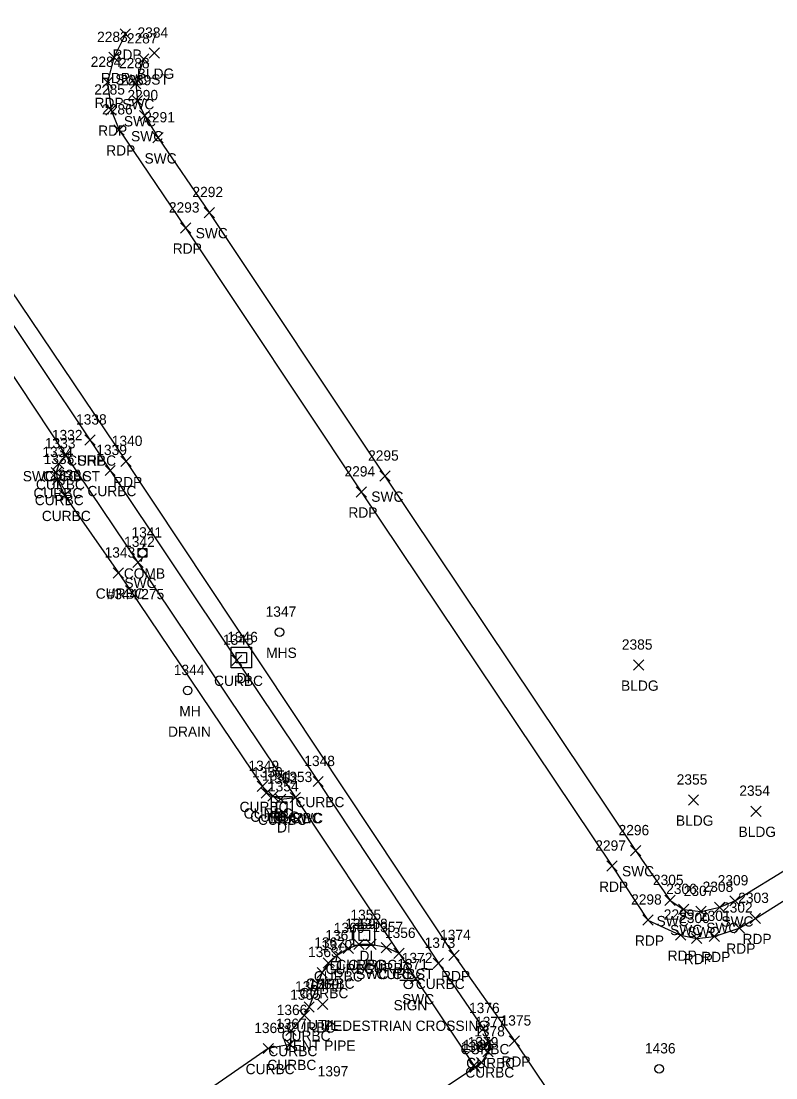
# Model space of a CAD drawing. Extents: x 1635588 to 1637550, y 621583 to 623638.
# Drawn here: x 1636890.8 to 1637037.4, y 622269.5 to 622475 of the extents above; entities that cross this region are included whole.
import ezdxf

# ---------------------------------------------------------------- set-up
doc = ezdxf.new("R2010")
doc.units = 0
for name, color, linetype in [('D_A', 7, 'Continuous'), ('D_I', 7, 'Continuous'), ('DS', 7, 'Continuous'), ('L_A', 7, 'Continuous'), ('L_I', 7, 'Continuous'), ('L_TIC', 7, 'Continuous'), ('P_A', 7, 'Continuous'), ('P_I', 7, 'Continuous'), ('P_TIC', 7, 'Continuous'), ('PET', 7, 'Continuous'), ('PSP', 7, 'Continuous'), ('R_A', 7, 'Continuous'), ('R_I', 7, 'Continuous'), ('R_TIC', 7, 'Continuous'), ('RC', 7, 'Continuous'), ('RSW', 7, 'Continuous'), ('S_A', 7, 'Continuous'), ('S_C', 7, 'Continuous'), ('S_I', 7, 'Continuous'), ('SSGN', 7, 'Continuous'), ('U_A', 7, 'Continuous'), ('U_C', 7, 'Continuous'), ('U_I', 7, 'Continuous'), ('UDEFAULT', 7, 'Continuous'), ('ULP', 7, 'Continuous'), ('UP', 7, 'Continuous'), ('USMH', 7, 'Continuous'), ('UUMH', 7, 'Continuous')]:
    doc.layers.add(name, color=color, linetype=linetype)

msp = doc.modelspace()

# ---------------------------------------------------------------- linework, layer by layer
at = {"layer": 'DS'}
for p, q in [((1636931.56, 622353.25), (1636935.56, 622353.25)), ((1636931.56, 622349.25), (1636931.56, 622353.25)), ((1636935.56, 622353.25), (1636935.56, 622349.25)), ((1636932.56, 622350.25), (1636932.56, 622352.25)), ((1636932.56, 622352.25), (1636934.56, 622352.25)), ((1636933.57, 622351.25), (1636933.57, 622351.25)), ((1636933.57, 622351.25), (1636933.57, 622351.25)), ((1636934.56, 622352.25), (1636934.56, 622350.25)), ((1636935.56, 622349.25), (1636931.56, 622349.25)), ((1636934.56, 622350.25), (1636932.56, 622350.25)), ((1636939.43, 622324.22), (1636943.43, 622324.22)), ((1636939.43, 622320.22), (1636939.43, 622324.22)), ((1636943.43, 622324.22), (1636943.43, 622320.22)), ((1636940.43, 622321.22), (1636940.43, 622323.22)), ((1636940.43, 622323.22), (1636942.43, 622323.22)), ((1636941.44, 622322.23), (1636941.44, 622322.23)), ((1636941.44, 622322.23), (1636941.44, 622322.23)), ((1636942.43, 622323.22), (1636942.43, 622321.22)), ((1636943.43, 622320.22), (1636939.43, 622320.22)), ((1636942.43, 622321.22), (1636940.43, 622321.22)), ((1636955.45, 622299.24), (1636959.45, 622299.24)), ((1636955.45, 622295.24), (1636955.45, 622299.24)), ((1636959.45, 622299.24), (1636959.45, 622295.24)), ((1636956.45, 622296.24), (1636956.45, 622298.24)), ((1636956.45, 622298.24), (1636958.45, 622298.24)), ((1636957.45, 622297.24), (1636957.45, 622297.24)), ((1636957.45, 622297.24), (1636957.45, 622297.24)), ((1636958.45, 622298.24), (1636958.45, 622296.24)), ((1636959.45, 622295.24), (1636955.45, 622295.24)), ((1636958.45, 622296.24), (1636956.45, 622296.24))]:
    msp.add_line(p, q, dxfattribs=at)
at = {"layer": 'L_TIC'}
for points in [[(1636915.66, 622467.77), (1636917.66, 622469.77)], [(1636917.66, 622467.77), (1636915.66, 622469.77)], [(1637009.74, 622348.79), (1637011.74, 622350.79)], [(1637011.74, 622348.79), (1637009.74, 622350.79)], [(1637020.4, 622322.55), (1637022.4, 622324.55)], [(1637022.4, 622322.55), (1637020.4, 622324.55)], [(1637032.56, 622320.37), (1637034.56, 622322.37)], [(1637034.56, 622320.37), (1637032.56, 622322.37)]]:
    msp.add_lwpolyline(points, dxfattribs=at)
at = {"layer": 'P_TIC'}
for points in [[(1636910.05, 622471.47), (1636912.05, 622473.47)], [(1636912.05, 622471.47), (1636910.05, 622473.47)], [(1636907.81, 622466.93), (1636909.81, 622468.93)], [(1636909.81, 622466.93), (1636907.81, 622468.93)], [(1636906.57, 622462.09), (1636908.57, 622464.09)], [(1636908.57, 622462.09), (1636906.57, 622464.09)], [(1636907.26, 622456.7), (1636909.26, 622458.7)], [(1636909.26, 622456.7), (1636907.26, 622458.7)], [(1636908.83, 622452.84), (1636910.83, 622454.84)], [(1636910.83, 622452.84), (1636908.83, 622454.84)], [(1636921.75, 622433.77), (1636923.75, 622435.77)], [(1636923.75, 622433.77), (1636921.75, 622435.77)], [(1636903.15, 622392.55), (1636905.15, 622394.55)], [(1636905.15, 622392.55), (1636903.15, 622394.55)], [(1636910.18, 622388.38), (1636912.18, 622390.38)], [(1636912.18, 622388.38), (1636910.18, 622390.38)], [(1636955.87, 622382.45), (1636957.87, 622384.45)], [(1636957.87, 622382.45), (1636955.87, 622384.45)], [(1637004.57, 622309.7), (1637006.57, 622311.7)], [(1637006.57, 622309.7), (1637004.57, 622311.7)], [(1637011.54, 622299.22), (1637013.54, 622301.22)], [(1637013.54, 622299.22), (1637011.54, 622301.22)], [(1637032.43, 622299.54), (1637034.43, 622301.54)], [(1637034.43, 622299.54), (1637032.43, 622301.54)], [(1637029.28, 622297.66), (1637031.28, 622299.66)], [(1637031.28, 622297.66), (1637029.28, 622299.66)], [(1637017.89, 622296.29), (1637019.89, 622298.29)], [(1637019.89, 622296.29), (1637017.89, 622298.29)], [(1637021.03, 622295.63), (1637023.03, 622297.63)], [(1637023.03, 622295.63), (1637021.03, 622297.63)], [(1637024.42, 622296.04), (1637026.42, 622298.04)], [(1637026.42, 622296.04), (1637024.42, 622298.04)], [(1636973.88, 622292.33), (1636975.88, 622294.33)], [(1636975.88, 622292.33), (1636973.88, 622294.33)], [(1636985.61, 622275.7), (1636987.61, 622277.7)], [(1636987.61, 622275.7), (1636985.61, 622277.7)]]:
    msp.add_lwpolyline(points, dxfattribs=at)
at = {"layer": 'PET'}
for points in [[(1636496.54, 623045.3), (1636533.69, 622970.65), (1636546.95, 622944.69), (1636557.06, 622926.23), (1636579, 622887.89), (1636603.72, 622849.48), (1636616.07, 622830.82), (1636647.79, 622783.76), (1636703.25, 622700.68), (1636737.08, 622649.81), (1636763.83, 622609.67), (1636812.95, 622535.62), (1636858.06, 622468.21), (1636878.24, 622438.26), (1636911.18, 622389.38), (1636974.88, 622293.33), (1636986.61, 622276.7), (1637016.63, 622231.99)], [(1636911.05, 622472.47), (1636908.81, 622467.93), (1636907.57, 622463.09), (1636908.26, 622457.7), (1636909.83, 622453.84), (1636922.75, 622434.77), (1636956.87, 622383.45), (1637005.57, 622310.7), (1637012.54, 622300.22), (1637018.89, 622297.29), (1637022.03, 622296.63), (1637025.42, 622297.04), (1637030.28, 622298.66), (1637033.43, 622300.54), (1637043.41, 622306.81)]]:
    msp.add_lwpolyline(points, dxfattribs=at)
at = {"layer": 'PSP'}
msp.add_lwpolyline([(1636412.61, 623220.07), (1636436.6, 623167.3), (1636456.23, 623125.07), (1636460.67, 623115.98), (1636475.52, 623084.87), (1636494.51, 623045.42), (1636524.16, 622986.51), (1636530.74, 622972.24), (1636554.07, 622925.3), (1636577.18, 622886.3), (1636601.72, 622847.41), (1636613.46, 622830.09), (1636645.38, 622782.47), (1636700.61, 622698.86), (1636734.28, 622648.07), (1636752.12, 622619.3), (1636752.46, 622616.81), (1636755.34, 622613.42), (1636810.04, 622534.39), (1636855.63, 622465.66), (1636874.76, 622437.49), (1636904.15, 622393.55)], dxfattribs=at)
at = {"layer": 'R_TIC'}
for points in [[(1636913.59, 622466.64), (1636915.59, 622468.64)], [(1636915.59, 622466.64), (1636913.59, 622468.64)], [(1636912.06, 622461.83), (1636914.06, 622463.83)], [(1636914.06, 622461.83), (1636912.06, 622463.83)], [(1636912.39, 622458.51), (1636914.39, 622460.51)], [(1636914.39, 622458.51), (1636912.39, 622460.51)], [(1636913.78, 622455.61), (1636915.78, 622457.61)], [(1636915.78, 622455.61), (1636913.78, 622457.61)], [(1636916.39, 622451.3), (1636918.39, 622453.3)], [(1636918.39, 622451.3), (1636916.39, 622453.3)], [(1636926.33, 622436.77), (1636928.33, 622438.77)], [(1636928.33, 622436.77), (1636926.33, 622438.77)], [(1636903.15, 622392.55), (1636905.15, 622394.55)], [(1636905.15, 622392.55), (1636903.15, 622394.55)], [(1636898.45, 622389.51), (1636900.45, 622391.51)], [(1636900.45, 622389.51), (1636898.45, 622391.51)], [(1636898.45, 622389.51), (1636900.45, 622391.51)], [(1636900.45, 622389.51), (1636898.45, 622391.51)], [(1636897.09, 622387.91), (1636899.09, 622389.91)], [(1636899.09, 622387.91), (1636897.09, 622389.91)], [(1636896.61, 622386.22), (1636898.61, 622388.22)], [(1636898.61, 622386.22), (1636896.61, 622388.22)], [(1636907.09, 622386.62), (1636909.09, 622388.62)], [(1636909.09, 622386.62), (1636907.09, 622388.62)], [(1636960.45, 622385.53), (1636962.45, 622387.53)], [(1636962.45, 622385.53), (1636960.45, 622387.53)], [(1636896.86, 622384.87), (1636898.86, 622386.87)], [(1636898.86, 622384.87), (1636896.86, 622386.87)], [(1636898.22, 622381.78), (1636900.22, 622383.78)], [(1636900.22, 622381.78), (1636898.22, 622383.78)], [(1636912.49, 622368.76), (1636914.49, 622370.76)], [(1636914.49, 622368.76), (1636912.49, 622370.76)], [(1636908.69, 622366.69), (1636910.69, 622368.69)], [(1636910.69, 622366.69), (1636908.69, 622368.69)], [(1636931.69, 622349.73), (1636933.69, 622351.73)], [(1636933.69, 622349.73), (1636931.69, 622351.73)], [(1636947.49, 622326.15), (1636949.49, 622328.15)], [(1636949.49, 622326.15), (1636947.49, 622328.15)], [(1636936.65, 622325.21), (1636938.65, 622327.21)], [(1636938.65, 622325.21), (1636936.65, 622327.21)], [(1636937.43, 622323.94), (1636939.43, 622325.94)], [(1636939.43, 622323.94), (1636937.43, 622325.94)], [(1636938.71, 622323.31), (1636940.71, 622325.31)], [(1636940.71, 622323.31), (1636938.71, 622325.31)], [(1636940.21, 622322.72), (1636942.21, 622324.72)], [(1636942.21, 622322.72), (1636940.21, 622324.72)], [(1636943.08, 622323.04), (1636945.08, 622325.04)], [(1636945.08, 622323.04), (1636943.08, 622325.04)], [(1636943.08, 622323.04), (1636945.08, 622325.04)], [(1636945.08, 622323.04), (1636943.08, 622325.04)], [(1637009.15, 622312.71), (1637011.15, 622314.71)], [(1637011.15, 622312.71), (1637009.15, 622314.71)], [(1637015.86, 622303.02), (1637017.86, 622305.02)], [(1637017.86, 622303.02), (1637015.86, 622305.02)], [(1637018.49, 622301.28), (1637020.49, 622303.28)], [(1637020.49, 622301.28), (1637018.49, 622303.28)], [(1637025.51, 622301.69), (1637027.51, 622303.69)], [(1637027.51, 622301.69), (1637025.51, 622303.69)], [(1637028.44, 622302.95), (1637030.44, 622304.95)], [(1637030.44, 622302.95), (1637028.44, 622304.95)], [(1637021.85, 622300.89), (1637023.85, 622302.89)], [(1637023.85, 622300.89), (1637021.85, 622302.89)], [(1636953.36, 622293.7), (1636955.36, 622295.7)], [(1636955.36, 622293.7), (1636953.36, 622295.7)], [(1636955.44, 622294.49), (1636957.44, 622296.49)], [(1636957.44, 622294.49), (1636955.44, 622296.49)], [(1636957.74, 622294.48), (1636959.74, 622296.48)], [(1636959.74, 622294.48), (1636957.74, 622296.48)], [(1636960.73, 622293.87), (1636962.73, 622295.87)], [(1636962.73, 622293.87), (1636960.73, 622295.87)], [(1636949.47, 622290.85), (1636951.47, 622292.85)], [(1636951.47, 622290.85), (1636949.47, 622292.85)], [(1636951.06, 622292.27), (1636953.06, 622294.27)], [(1636953.06, 622292.27), (1636951.06, 622294.27)], [(1636963.21, 622292.73), (1636965.21, 622294.73)], [(1636965.21, 622292.73), (1636963.21, 622294.73)], [(1636963.21, 622292.73), (1636965.21, 622294.73)], [(1636965.21, 622292.73), (1636963.21, 622294.73)], [(1636970.86, 622290.81), (1636972.86, 622292.81)], [(1636972.86, 622290.81), (1636970.86, 622292.81)], [(1636948.27, 622289.01), (1636950.27, 622291.01)], [(1636950.27, 622289.01), (1636948.27, 622291.01)], [(1636966.42, 622287.84), (1636968.42, 622289.84)], [(1636968.42, 622287.84), (1636966.42, 622289.84)], [(1636944.79, 622280.71), (1636946.79, 622282.71)], [(1636946.79, 622280.71), (1636944.79, 622282.71)], [(1636945.74, 622282.33), (1636947.74, 622284.33)], [(1636947.74, 622282.33), (1636945.74, 622284.33)], [(1636942.24, 622277.74), (1636944.24, 622279.74)], [(1636944.24, 622277.74), (1636942.24, 622279.74)], [(1636979.55, 622278.12), (1636981.55, 622280.12)], [(1636981.55, 622278.12), (1636979.55, 622280.12)], [(1636942.04, 622275.05), (1636944.04, 622277.05)], [(1636944.04, 622275.05), (1636942.04, 622277.05)], [(1636980.67, 622275.42), (1636982.67, 622277.42)], [(1636982.67, 622275.42), (1636980.67, 622277.42)], [(1636937.81, 622274.24), (1636939.81, 622276.24)], [(1636939.81, 622274.24), (1636937.81, 622276.24)], [(1636980.49, 622273.59), (1636982.49, 622275.59)], [(1636982.49, 622273.59), (1636980.49, 622275.59)], [(1636977.75, 622270.94), (1636979.75, 622272.94)], [(1636979.75, 622270.94), (1636977.75, 622272.94)], [(1636977.98, 622270.56), (1636979.98, 622272.56)], [(1636979.98, 622270.56), (1636977.98, 622272.56)], [(1636979.25, 622271.48), (1636981.25, 622273.48)], [(1636981.25, 622271.48), (1636979.25, 622273.48)]]:
    msp.add_lwpolyline(points, dxfattribs=at)
at = {"layer": 'RC'}
for points in [[(1636904.15, 622393.55), (1636908.09, 622387.62), (1636932.69, 622350.73), (1636948.49, 622327.15), (1636971.86, 622291.81), (1636980.55, 622279.12), (1636981.67, 622276.42), (1636981.49, 622274.59), (1636980.25, 622272.48), (1636978.98, 622271.56), (1636939.82, 622245.4), (1636936.81, 622243.85), (1636933.44, 622243.25), (1636930.33, 622243.36), (1636927.36, 622244.02), (1636924.3, 622245.4), (1636922.37, 622246.84), (1636920.75, 622248.49), (1636918.9, 622251.53), (1636918.26, 622253.09), (1636917.77, 622255.72), (1636917.56, 622258.05), (1636918.63, 622260.41), (1636920.18, 622262.35)], [(1636899.45, 622390.51), (1636898.09, 622388.91), (1636897.61, 622387.22), (1636897.86, 622385.87), (1636899.22, 622382.78), (1636909.69, 622367.69), (1636937.65, 622326.21), (1636938.43, 622324.94), (1636939.71, 622324.31), (1636941.21, 622323.72), (1636944.08, 622324.04)], [(1636964.21, 622293.73), (1636961.73, 622294.87), (1636958.74, 622295.48), (1636956.44, 622295.49), (1636954.36, 622294.7), (1636952.06, 622293.27), (1636950.47, 622291.85), (1636949.27, 622290.01), (1636946.74, 622283.33), (1636945.79, 622281.71), (1636943.24, 622278.74), (1636943.04, 622276.05), (1636938.81, 622275.24), (1636920.18, 622262.35)]]:
    msp.add_lwpolyline(points, dxfattribs=at)
at = {"layer": 'RSW'}
for points in [[(1636914.59, 622467.64), (1636913.06, 622462.83), (1636913.39, 622459.51), (1636914.78, 622456.61), (1636917.39, 622452.3), (1636927.33, 622437.77), (1636961.45, 622386.53), (1637010.15, 622313.71), (1637016.86, 622304.02), (1637019.49, 622302.28), (1637022.85, 622301.89), (1637026.51, 622302.69), (1637029.44, 622303.95), (1637040.61, 622310.82)], [(1636867.97, 622438.29), (1636881.03, 622418.32), (1636899.45, 622390.51), (1636913.49, 622369.76), (1636944.08, 622324.04), (1636964.21, 622293.73), (1636967.42, 622288.84), (1636978.75, 622271.94)]]:
    msp.add_lwpolyline(points, dxfattribs=at)
at = {"layer": 'SSGN'}
for p, q in [((1636964.36, 622288.52), (1636967.7, 622288.52)), ((1636966.01, 622287.68), (1636966.01, 622287.68))]:
    msp.add_line(p, q, dxfattribs=at)
msp.add_circle((1636966.01, 622287.68), 0.833, dxfattribs=at)
at = {"layer": 'UDEFAULT'}
for points in [[(1636948.39, 622282.81), (1636950.39, 622284.81)], [(1636950.39, 622282.81), (1636948.39, 622284.81)]]:
    msp.add_lwpolyline(points, dxfattribs=at)
at = {"layer": 'ULP'}
for p, q in [((1636952.08, 622293.01), (1636951.92, 622292.18)), ((1636951.08, 622290.51), (1636951.08, 622292.18)), ((1636951.08, 622292.18), (1636952.75, 622292.18)), ((1636951.92, 622291.34), (1636951.92, 622291.34)), ((1636952.75, 622292.18), (1636952.75, 622290.51)), ((1636952.75, 622290.51), (1636951.08, 622290.51)), ((1636951.67, 622289.68), (1636951.92, 622290.51))]:
    msp.add_line(p, q, dxfattribs=at)
at = {"layer": 'UP'}
for p, q in [((1636914.61, 622373.26), (1636914.36, 622372.43)), ((1636913.52, 622370.76), (1636913.52, 622372.43)), ((1636913.52, 622372.43), (1636915.19, 622372.43)), ((1636914.36, 622371.59), (1636914.36, 622371.59)), ((1636915.19, 622372.43), (1636915.19, 622370.76)), ((1636915.19, 622370.76), (1636913.52, 622370.76)), ((1636914.11, 622369.93), (1636914.36, 622370.76))]:
    msp.add_line(p, q, dxfattribs=at)
msp.add_circle((1636914.36, 622371.59), 0.833, dxfattribs=at)
at = {"layer": 'USMH'}
for p, q in [((1636940.97, 622356.18), (1636940.97, 622356.18)), ((1636941.8, 622356.18), (1636941.8, 622356.18)), ((1637014.71, 622271.28), (1637014.71, 622271.28)), ((1637015.54, 622271.28), (1637015.54, 622271.28))]:
    msp.add_line(p, q, dxfattribs=at)
for centre in [(1636940.97, 622356.18), (1637014.71, 622271.28)]:
    msp.add_circle(centre, 0.833, dxfattribs=at)
at = {"layer": 'UUMH'}
for p, q in [((1636923.14, 622344.84), (1636923.14, 622344.84)), ((1636923.98, 622344.84), (1636923.98, 622344.84))]:
    msp.add_line(p, q, dxfattribs=at)
msp.add_circle((1636923.14, 622344.84), 0.833, dxfattribs=at)

# ---------------------------------------------------------------- texts
at = {"layer": 'D_A'}
for p in [(1636932.62, 622346.25), (1636940.49, 622317.23), (1636956.51, 622292.24)]:
    msp.add_text('DI', height=2, dxfattribs=at).set_placement(p)
at = {"layer": 'D_I'}
for s, p in [('1346', (1636930.82, 622354.25)), ('1354', (1636938.74, 622325.23)), ('1355', (1636954.76, 622300.24))]:
    msp.add_text(s, height=2, dxfattribs=at).set_placement(p)
at = {"layer": 'L_A'}
for p in [(1636913.25, 622463.77), (1637007.33, 622344.79), (1637017.99, 622318.55), (1637030.15, 622316.37)]:
    msp.add_text('BLDG', height=2, dxfattribs=at).set_placement(p)
at = {"layer": 'L_I'}
for s, p in [('2384', (1636913.4, 622471.77)), ('2385', (1637007.48, 622352.79)), ('2355', (1637018.14, 622326.55)), ('2354', (1637030.3, 622324.37))]:
    msp.add_text(s, height=2, dxfattribs=at).set_placement(p)
at = {"layer": 'P_A'}
for s, p in [('RDP', (1636908.54, 622467.47)), ('RDP', (1636906.3, 622462.93)), ('RDP', (1636905.06, 622458.09)), ('RDP', (1636905.75, 622452.7)), ('RDP', (1636907.32, 622448.84)), ('RDP', (1636920.24, 622429.77)), ('SHP', (1636901.69, 622388.55)), ('RDP', (1636908.67, 622384.38)), ('RDP', (1636954.36, 622378.45)), ('RDP', (1637003.06, 622305.7)), ('RDP', (1637010.03, 622295.22)), ('RDP', (1637030.92, 622295.54)), ('RDP', (1637027.77, 622293.66)), ('RDP', (1637016.38, 622292.29)), ('RDP', (1637019.52, 622291.63)), ('RDP', (1637022.91, 622292.04)), ('RDP', (1636972.36, 622288.33)), ('RDP', (1636984.1, 622271.7))]:
    msp.add_text(s, height=2, dxfattribs=at).set_placement(p)
at = {"layer": 'P_I'}
for s, p in [('2283', (1636905.55, 622470.93)), ('2284', (1636904.31, 622466.09)), ('2285', (1636905, 622460.7)), ('2286', (1636906.52, 622456.84)), ('2293', (1636919.49, 622437.77)), ('1338', (1636901.46, 622396.55)), ('1340', (1636908.4, 622392.38)), ('2294', (1636953.61, 622386.45)), ('2297', (1637002.32, 622313.7)), ('2298', (1637009.28, 622303.22)), ('2303', (1637030.09, 622303.54)), ('2302', (1637026.94, 622301.66)), ('2299', (1637015.62, 622300.29)), ('2300', (1637018.61, 622299.63)), ('2301', (1637022.65, 622300.04)), ('1374', (1636972.18, 622296.33)), ('1375', (1636983.92, 622279.7))]:
    msp.add_text(s, height=2, dxfattribs=at).set_placement(p)
at = {"layer": 'R_A'}
for s, p in [('SWC ST', (1636909.09, 622462.64)), ('SWC', (1636910.42, 622457.83)), ('SWC', (1636910.75, 622454.51)), ('SWC', (1636912.14, 622451.61)), ('SWC', (1636914.76, 622447.3)), ('SWC', (1636924.7, 622432.77)), ('CURBC', (1636899.73, 622388.55)), ('SWC CC ST', (1636891.11, 622385.51)), ('CURBC', (1636895.03, 622385.51)), ('CURBC', (1636893.67, 622383.91)), ('CURBC', (1636893.19, 622382.22)), ('CURBC', (1636903.67, 622382.62)), ('SWC', (1636958.81, 622381.53)), ('CURBC', (1636893.44, 622380.87)), ('CURBC', (1636894.81, 622377.78)), ('SWC', (1636910.85, 622364.76)), ('CURBC', (1636905.28, 622362.69)), ('CURBC', (1636928.27, 622345.73)), ('CURBC', (1636944.08, 622322.15)), ('CURBC', (1636933.23, 622321.21)), ('CURBC', (1636934.02, 622319.94)), ('CURBC', (1636935.29, 622319.31)), ('CURBC', (1636936.79, 622318.72)), ('CC SWC', (1636938.61, 622319.04)), ('CURBC', (1636939.66, 622319.04)), ('SWC', (1637007.51, 622308.71)), ('SWC', (1637014.22, 622299.02)), ('SWC', (1637016.85, 622297.28)), ('SWC', (1637023.87, 622297.69)), ('SWC', (1637026.81, 622298.95)), ('SWC', (1637020.21, 622296.89)), ('CURBC', (1636949.94, 622289.7)), ('CURBC', (1636952.02, 622290.49)), ('CURBC', (1636954.32, 622290.48)), ('SWC CC ST', (1636955.87, 622288.73)), ('CURBC', (1636957.32, 622289.87)), ('CURBC', (1636959.8, 622288.73)), ('CURBC', (1636946.05, 622286.85)), ('CURBC', (1636947.65, 622288.27)), ('CURBC', (1636967.45, 622286.81)), ('CURBC', (1636944.85, 622285.01)), ('SWC', (1636964.79, 622283.84)), ('CURBC', (1636941.38, 622276.71)), ('CURBC', (1636942.32, 622278.33)), ('CURBC', (1636938.82, 622273.74)), ('CURBC', (1636976.13, 622274.12)), ('CURBC', (1636934.4, 622270.24)), ('CURBC', (1636938.62, 622271.05)), ('CURBC', (1636977.25, 622271.42)), ('CURBC', (1636977.07, 622269.59))]:
    msp.add_text(s, height=2, dxfattribs=at).set_placement(p)
at = {"layer": 'R_I'}
for s, p in [('2287', (1636911.33, 622470.64)), ('2288', (1636909.8, 622465.83)), ('2289', (1636910.12, 622462.51)), ('2290', (1636911.44, 622459.61)), ('2291', (1636914.7, 622455.3)), ('2292', (1636924.07, 622440.77)), ('1338', (1636901.46, 622396.55)), ('1332', (1636896.76, 622393.51)), ('1332', (1636896.76, 622393.51)), ('1333', (1636895.4, 622391.91)), ('1334', (1636894.92, 622390.22)), ('1339', (1636905.39, 622390.62)), ('2295', (1636958.19, 622389.53)), ('1335', (1636895.16, 622388.87)), ('1336', (1636896.48, 622385.78)), ('1342', (1636910.8, 622372.76)), ('1343', (1636907, 622370.69)), ('1345', (1636930, 622353.73)), ('1348', (1636945.8, 622330.15)), ('1349', (1636934.95, 622329.21)), ('1350', (1636935.65, 622327.94)), ('1351', (1636937.58, 622327.31)), ('1352', (1636938.52, 622326.72)), ('1353', (1636941.39, 622327.04)), ('1353', (1636941.39, 622327.04)), ('2296', (1637006.84, 622316.71)), ('2305', (1637013.52, 622307.02)), ('2306', (1637016.09, 622305.28)), ('2308', (1637023.17, 622305.69)), ('2309', (1637026.1, 622306.95)), ('2307', (1637019.51, 622304.89)), ('1360', (1636951.53, 622297.7)), ('1359', (1636953.74, 622298.49)), ('1358', (1636956.05, 622298.48)), ('1357', (1636959.04, 622297.87)), ('1361', (1636949.89, 622296.27)), ('1356', (1636961.46, 622296.73)), ('1356', (1636961.46, 622296.73)), ('1363', (1636946.53, 622293.01)), ('1362', (1636947.73, 622294.85)), ('1373', (1636969.17, 622294.81)), ('1372', (1636964.73, 622291.84)), ('1365', (1636943.05, 622284.71)), ('1364', (1636944, 622286.33)), ('1366', (1636940.44, 622281.74)), ('1376', (1636977.8, 622282.12)), ('1367', (1636940.3, 622279.05)), ('1377', (1636978.98, 622279.42)), ('1368', (1636936.07, 622278.24)), ('1378', (1636978.8, 622277.59)), ('1380', (1636976.2, 622274.56)), ('1381', (1636976.62, 622274.94)), ('1379', (1636977.55, 622275.48))]:
    msp.add_text(s, height=2, dxfattribs=at).set_placement(p)
at = {"layer": 'S_A'}
msp.add_text('SIGN', height=2, dxfattribs=at).set_placement((1636963.15, 622282.66))
at = {"layer": 'S_C'}
msp.add_text('PEDESTRIAN CROSSING', height=2, dxfattribs=at).set_placement((1636949.59, 622278.66))
at = {"layer": 'S_I'}
msp.add_text('1371', height=2, dxfattribs=at).set_placement((1636963.86, 622290.66))
at = {"layer": 'U_A'}
for s, p in [('COMB', (1636910.74, 622366.59)), ('MHS', (1636938.39, 622351.18)), ('MH', (1636921.51, 622339.84)), ('LI', (1636951.02, 622286.34)), ('UTIL', (1636946.55, 622278.81))]:
    msp.add_text(s, height=2, dxfattribs=at).set_placement(p)
at = {"layer": 'U_C'}
for s, p in [('#344/275', (1636907.43, 622362.59)), ('DRAIN', (1636919.33, 622335.84)), ('VENT PIPE', (1636941.78, 622274.81))]:
    msp.add_text(s, height=2, dxfattribs=at).set_placement(p)
at = {"layer": 'U_I'}
for s, p in [('1341', (1636912.23, 622374.59)), ('1347', (1636938.28, 622359.18)), ('1344', (1636920.45, 622347.84)), ('1370', (1636949.14, 622294.34)), ('1369', (1636946.64, 622286.81)), ('1436', (1637011.96, 622274.28)), ('1397', (1636948.4, 622269.82))]:
    msp.add_text(s, height=2, dxfattribs=at).set_placement(p)

doc.saveas('drawing.dxf')
